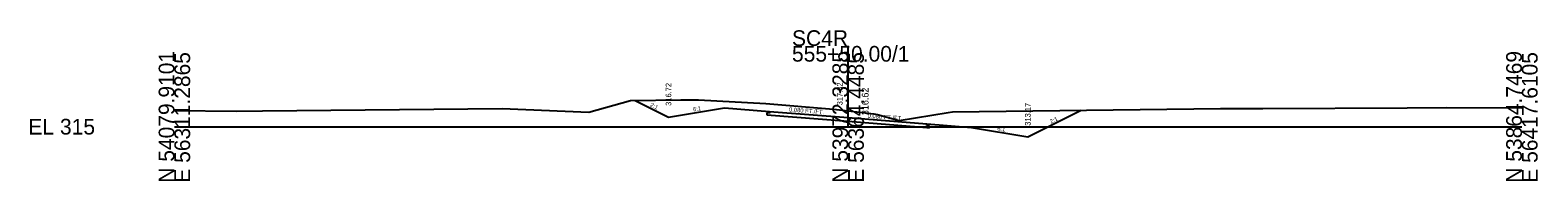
# Model space of a CAD drawing. Extents: x 9740 to 17409, y 8856 to 28416.
# Drawn here: x 12740.2 to 13008.7, y 16361.7 to 16388.6 of the extents above; entities that cross this region are included whole.
import ezdxf

# ---------------------------------------------------------------- set-up
doc = ezdxf.new("R2010")
doc.units = 0
for name, color, linetype in [('Level 10', 7, 'Continuous'), ('Level 11', 7, 'Continuous'), ('Level 12', 7, 'Continuous'), ('Level 32', 7, 'Continuous'), ('Level 33', 7, 'Continuous'), ('Level 59', 7, 'Continuous'), ('Level 6', 7, 'Continuous'), ('Level 60', 7, 'Continuous'), ('Level 63', 7, 'Continuous'), ('Level 7', 7, 'Continuous')]:
    doc.layers.add(name, color=color, linetype=linetype)

msp = doc.modelspace()

# ---------------------------------------------------------------- linework, layer by layer
at = {"layer": 'Level 11'}
for p, q in [((12871.85, 16373.82), (12871.35, 16373.86)), ((12871.35, 16373.86), (12871.35, 16373.52)), ((12871.85, 16374.12), (12871.85, 16373.82)), ((12899.85, 16371.58), (12899.85, 16371.88)), ((12900.35, 16371.54), (12899.85, 16371.58)), ((12899.85, 16371.24), (12900.35, 16371.2)), ((12900.35, 16371.2), (12900.35, 16371.54))]:
    msp.add_line(p, q, dxfattribs=at)
at = {"layer": 'Level 12'}
for p, q in [((12871.35, 16373.52), (12885.85, 16372.36)), ((12885.85, 16372.36), (12899.85, 16371.24))]:
    msp.add_line(p, q, dxfattribs=at)
at = {"layer": 'Level 59'}
for p, q in [((12871.85, 16374.12), (12885.85, 16373)), ((12885.85, 16373), (12899.85, 16371.88))]:
    msp.add_line(p, q, dxfattribs=at)
at = {"layer": 'Level 6'}
for p, q in [((12863.85, 16374.76), (12871.85, 16374.12)), ((12899.85, 16371.88), (12907.85, 16371.22))]:
    msp.add_line(p, q, dxfattribs=at)
at = {"layer": 'Level 60'}
for p, q in [((12839.65, 16373.95), (12847.06, 16376.04)), ((12847.06, 16376.04), (12856.05, 16376.15)), ((12856.05, 16376.15), (12859.22, 16376.19)), ((12859.22, 16376.19), (12871.21, 16375.52)), ((12871.21, 16375.52), (12883.24, 16374.49)), ((12765.85, 16374.25), (12776.84, 16374.16)), ((12776.84, 16374.16), (12781.54, 16374.21)), ((12781.54, 16374.21), (12824.23, 16374.63)), ((12824.23, 16374.63), (12839.65, 16373.95)), ((12883.24, 16374.49), (12885.85, 16374.2)), ((12885.85, 16374.2), (12890.42, 16373.69)), ((12890.42, 16373.69), (12891.09, 16373.57)), ((12891.09, 16373.57), (12894.93, 16372.49)), ((12894.93, 16372.49), (12903.65, 16373.94)), ((12903.65, 16373.94), (12904.42, 16374.03)), ((12904.42, 16374.03), (12952.18, 16374.61)), ((12952.18, 16374.61), (12959.74, 16374.63)), ((12959.74, 16374.63), (12985.4, 16374.74)), ((12985.4, 16374.74), (12992.49, 16374.8)), ((12992.49, 16374.8), (13005.85, 16374.74))]:
    msp.add_line(p, q, dxfattribs=at)
at = {"layer": 'Level 63'}
for p, q in [((12885.85, 16371.38), (12885.85, 16385.8)), ((12765.85, 16371.38), (12885.85, 16371.38)), ((12885.85, 16371.38), (13005.85, 16371.38))]:
    msp.add_line(p, q, dxfattribs=at)
at = {"layer": 'Level 7'}
for p, q in [((12847.94, 16376.05), (12853.85, 16373.1)), ((12853.85, 16373.1), (12863.85, 16374.76)), ((12917.85, 16369.55), (12927.37, 16374.31)), ((12907.85, 16371.22), (12917.85, 16369.55))]:
    msp.add_line(p, q, dxfattribs=at)

# ---------------------------------------------------------------- texts
at = {"layer": 'Level 10'}
msp.add_text('317.82', height=1, rotation=90, dxfattribs=at).set_placement((12884.85, 16375.2))
at = {"layer": 'Level 32'}
for s, rotation, p in [('2:1', 333.435, (12850.5, 16375.05)), ('6:1', 9.4623, (12858.29, 16374.09)), ('0.080 FT./FT.', 355.4261, (12875.29, 16374.1)), ('0.080 FT./FT.', 355.4261, (12889.29, 16372.98)), ('2:1', 26.5651, (12921.99, 16371.9)), ('6:1', 350.5377, (12912.37, 16370.72))]:
    msp.add_text(s, height=0.75, rotation=rotation, dxfattribs=at).set_placement(p)
at = {"layer": 'Level 33'}
for s, p in [('316.72', (12854.35, 16375.1)), ('313.17', (12918.35, 16371.55))]:
    msp.add_text(s, height=1, rotation=90, dxfattribs=at).set_placement(p)
at = {"layer": 'Level 59'}
msp.add_text(' 316.62', height=1.2, rotation=90, dxfattribs=at).set_placement((12889.48, 16373))
at = {"layer": 'Level 63'}
for s, p in [('SC4R', (12875.85, 16385.8)), ('555+50.00/1', (12875.85, 16383)), ('EL 315', (12739.85, 16369.98))]:
    msp.add_text(s, height=2.8, dxfattribs=at).set_placement(p)
for s, p in [('N 54079.9101', (12765.85, 16361.38)), ('E 56311.2865', (12768.65, 16361.38)), ('N 53972.3285', (12885.85, 16361.38)), ('E 56364.4485', (12888.65, 16361.38)), ('N 53864.7469', (13005.85, 16361.38)), ('E 56417.6105', (13008.65, 16361.38))]:
    msp.add_text(s, height=2.8, rotation=90, dxfattribs=at).set_placement(p)

doc.saveas('drawing.dxf')
